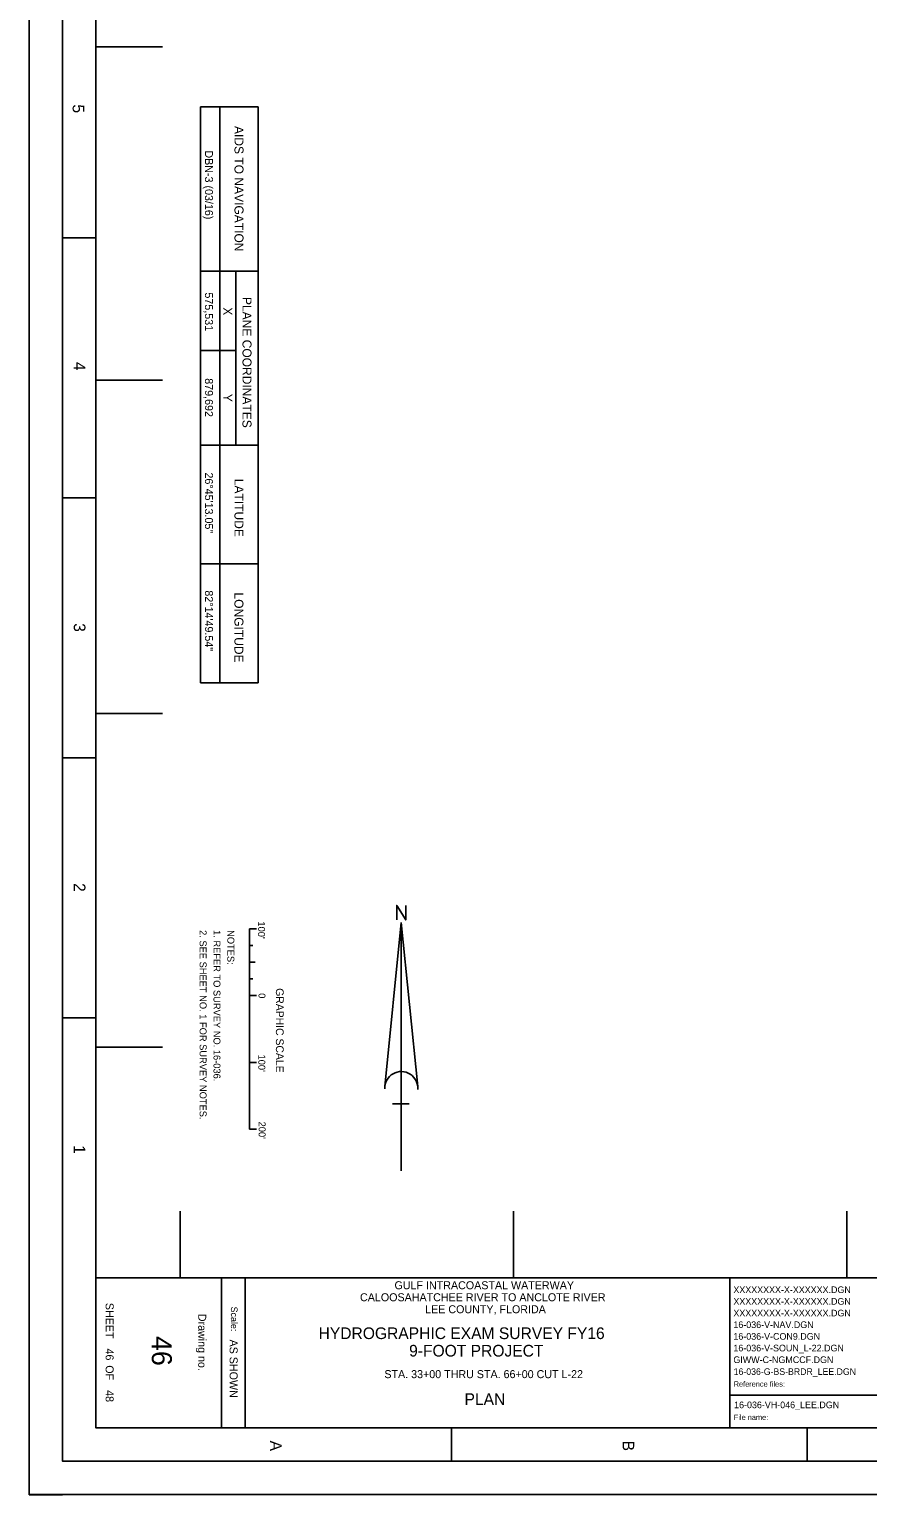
# Model space of a CAD drawing. Extents: x 573774 to 577174, y 877329 to 881729.
# Drawn here: x 573774 to 575031, y 877329 to 879526 of the extents above; entities that cross this region are included whole.
import ezdxf

# ---------------------------------------------------------------- set-up
doc = ezdxf.new("R2010")
doc.units = 0
for name, color, linetype in [('G-ANNO-NPLT', 7, 'Continuous'), ('G-ANNO-TEXT-DRWG', 7, 'Continuous'), ('G-ANNO-TEXT-PROJ', 7, 'Continuous'), ('G-ANNO-TEXT-TTLB', 7, 'Continuous'), ('G-ANNO-TTLB', 7, 'Continuous'), ('V-ANNO-NOTE', 7, 'Continuous'), ('V-ANNO-SCHD', 7, 'Continuous'), ('V-ANNO-SYMB', 7, 'Continuous'), ('V-TOPO-COOR-STAT', 7, 'Continuous')]:
    doc.layers.add(name, color=color, linetype=linetype)

msp = doc.modelspace()

# ---------------------------------------------------------------- linework, layer by layer
at = {"layer": 'G-ANNO-NPLT'}
msp.add_lwpolyline([(577173.7, 881728.7), (577173.7, 877328.7), (573773.7, 877328.7), (573773.7, 881728.7)], close=True, dxfattribs=at)
msp.add_lwpolyline([(573823.7, 877328.6), (573773.7, 877328.6), (573773.7, 877378.6)], dxfattribs=at)
at = {"layer": 'G-ANNO-TTLB'}
for p, q in [((573823.7, 879213.7), (573873.7, 879213.7)), ((573823.7, 878823.7), (573873.7, 878823.7)), ((573823.7, 878433.7), (573873.7, 878433.7)), ((573823.7, 878043.7), (573873.7, 878043.7)), ((577073.7, 877653.8), (573873.7, 877653.8)), ((574061.8, 877653.8), (574061.8, 877428.7)), ((574097.5, 877653.8), (574097.5, 877428.7)), ((574824.5, 877653.8), (574824.5, 877428.7)), ((575175.9, 877478), (574824.5, 877478)), ((574407, 877378.7), (574407, 877428.7)), ((574940.3, 877378.7), (574940.3, 877428.7))]:
    msp.add_line(p, q, dxfattribs=at)
for points in [[(573823.7, 881678.7), (573823.7, 877378.7), (577123.7, 877378.7), (577123.7, 881678.7)], [(577073.7, 877428.7), (577073.7, 881553.7), (573873.7, 881553.7), (573873.7, 877428.7)]]:
    msp.add_lwpolyline(points, close=True, dxfattribs=at)
at = {"layer": 'V-ANNO-NOTE'}
for p, q in [((574104.1, 878177), (574104.1, 877877)), ((574104.1, 878177), (574114.5, 878177)), ((574104.1, 878152), (574108.9, 878152)), ((574104.1, 878127), (574112.6, 878127)), ((574104.1, 878102), (574108.9, 878102)), ((574104.1, 878077), (574114.5, 878077)), ((574104.1, 878077), (574109.1, 878077)), ((574104.1, 878077), (574114.5, 878077)), ((574104.1, 877977), (574114.5, 877977)), ((574104.1, 877877), (574114.5, 877877))]:
    msp.add_line(p, q, dxfattribs=at)
at = {"layer": 'V-ANNO-SCHD'}
for p, q in [((574030.4, 879410.1), (574030.4, 878546.1)), ((574117.1, 879410.1), (574030.4, 879410.1)), ((574059.3, 879410.1), (574059.3, 878546.1)), ((574117.1, 879410.1), (574117.1, 878546.1)), ((574117.1, 879163.5), (574030.4, 879163.5)), ((574083.4, 879163.5), (574083.4, 878902.8)), ((574083.4, 879044.6), (574030.4, 879044.6)), ((574117.1, 878902.8), (574030.4, 878902.8)), ((574117.1, 878724.4), (574030.4, 878724.4)), ((574030.4, 878546.1), (574117.1, 878546.1))]:
    msp.add_line(p, q, dxfattribs=at)
at = {"layer": 'V-ANNO-SYMB'}
for p, q in [((574307, 877940.9), (574331.7, 878186.7)), ((574331.7, 877814.3), (574331.7, 878186.7)), ((574356.4, 877940.9), (574331.7, 878186.7)), ((574343.5, 877914.9), (574318.7, 877914.9))]:
    msp.add_line(p, q, dxfattribs=at)
msp.add_lwpolyline([(574324.9, 878190.6), (574324.9, 878212.4), (574338.4, 878190.6), (574338.4, 878212.4)], dxfattribs=at)
msp.add_arc((574331.7, 877938.4), 24.8, 355.2984, 182.0673, dxfattribs=at)
at = {"layer": 'V-TOPO-COOR-STAT'}
for p, q in [((573873.7, 879500), (573973.5, 879500)), ((573873.7, 879000), (573973.5, 879000)), ((573873.7, 878500), (573973.5, 878500)), ((573873.7, 878000), (573973.5, 878000)), ((574000, 877653.8), (574000, 877753.8)), ((574500, 877653.8), (574500, 877753.8)), ((575000, 877653.8), (575000, 877753.8))]:
    msp.add_line(p, q, dxfattribs=at)

# ---------------------------------------------------------------- texts
at = {"layer": 'G-ANNO-TEXT-DRWG'}
for s, height, rotation, p in [('XXXXXXXX-X-XXXXXX.DGN', 10, 360, (574829.8, 877631)), ('XXXXXXXX-X-XXXXXX.DGN', 10, 360, (574829.8, 877613.5)), ('XXXXXXXX-X-XXXXXX.DGN', 10, 360, (574829.8, 877596)), ('16-036-V-NAV.DGN', 10, 360, (574829.8, 877578.5)), ('46', 30, 270, (573957.5, 877566.5)), ('16-036-V-CON9.DGN', 10, 360, (574829.8, 877561)), (' 46          48', 12, 270, (573888.2, 877552.3)), ('16-036-V-SOUN_L-22.DGN', 10, 360, (574829.8, 877543.5)), ('GIWW-C-NGMCCF.DGN', 10, 360, (574829.8, 877526)), ('STA. 33+00 THRU STA. 66+00 CUT L-22', 12, 360, (574306.3, 877503.4)), ('PLAN', 17.5, 360, (574426.5, 877463.2)), ('16-036-VH-046_LEE.DGN', 10, 360, (574830.9, 877458.3))]:
    msp.add_text(s, height=height, rotation=rotation, dxfattribs=at).set_placement(p)
at = {"layer": 'G-ANNO-TEXT-PROJ'}
for s, height, p in [('CALOOSAHATCHEE RIVER TO ANCLOTE RIVER', 12, (574269.8, 877618.7)), ('GULF INTRACOASTAL WATERWAY', 12, (574321.5, 877636.7)), ('LEE COUNTY, FLORIDA', 12, (574367.5, 877600.7)), ('HYDROGRAPHIC EXAM SURVEY FY16', 17.5, (574207.6, 877562)), ('9-FOOT PROJECT', 17.5, (574343.4, 877535.8)), ('16-036-G-BS-BRDR_LEE.DGN', 9.8, (574830.2, 877508.3))]:
    msp.add_text(s, height=height, rotation=360, dxfattribs=at).set_placement(p)
at = {"layer": 'G-ANNO-TEXT-TTLB'}
for s, height, rotation, p in [('SHEET         OF', 12, 270, (573888.2, 877616.3)), ('Scale:', 10, 270, (574076.1, 877610.7)), ('Drawing no.', 12, 270, (574027.1, 877599.9)), ('AS SHOWN', 12, 270, (574074.2, 877561.3)), ('Reference files:', 8, 360, (574830.3, 877490.6)), ('File name:', 8, 360, (574830.5, 877440.7))]:
    msp.add_text(s, height=height, rotation=rotation, dxfattribs=at).set_placement(p)
at = {"layer": 'G-ANNO-TTLB'}
for s, p in [('5', (573838.7, 879413.6)), ('4', (573840.4, 879027.4)), ('3', (573840.4, 878635.6)), ('2', (573840.4, 878245.8)), ('1', (573840.4, 877852.7)), ('A', (574134.9, 877409.7)), ('B', (574663.6, 877409.7))]:
    msp.add_text(s, height=17.5, rotation=270, dxfattribs=at).set_placement(p)
at = {"layer": 'V-ANNO-NOTE'}
for s, height, p in [("100'", 10.42, (574116.8, 878188.3)), ('2. SEE SHEET NO. 1 FOR SURVEY NOTES.', 10.416, (574029.2, 878175.3)), ('1. REFER TO SURVEY NO. 16-036.', 10.416, (574050, 878175.3)), ('NOTES:', 10.42, (574070.8, 878175.3)), ('0', 10.4, (574117.5, 878080.7)), ('GRAPHIC SCALE', 11.666, (574143.6, 878088.2)), ("100'", 10.42, (574117.2, 877988.7)), ("200'", 10.42, (574117.7, 877888.1))]:
    msp.add_text(s, height=height, rotation=270, dxfattribs=at).set_placement(p)
at = {"layer": 'V-ANNO-SCHD'}
for s, height, p in [('AIDS TO NAVIGATION', 13.471, (574081.5, 879381.2)), ('PLANE COORDINATES', 13.471, (574093.5, 879124.8)), ('X', 13.5, (574064.6, 879109.3)), ('Y', 13.5, (574064.6, 878979.6)), ('LATITUDE', 13.47, (574081.5, 878852.1)), ('LONGITUDE', 13.47, (574081.4, 878681.6))]:
    msp.add_text(s, height=height, rotation=270.0001, dxfattribs=at).set_placement(p)
at = {"layer": 'V-ANNO-SYMB'}
for s, p in [('DBN-3 (03/16)', (574037.2, 879344.6)), ('575,531', (574037.2, 879131.6)), ('879,692', (574037.2, 879002.9)), ('26%%D45\'13.05"', (574037.2, 878861.6)), ('82%%D14\'49.54"', (574037.2, 878684.8))]:
    msp.add_text(s, height=12, rotation=270, dxfattribs=at).set_placement(p)

doc.saveas('drawing.dxf')
